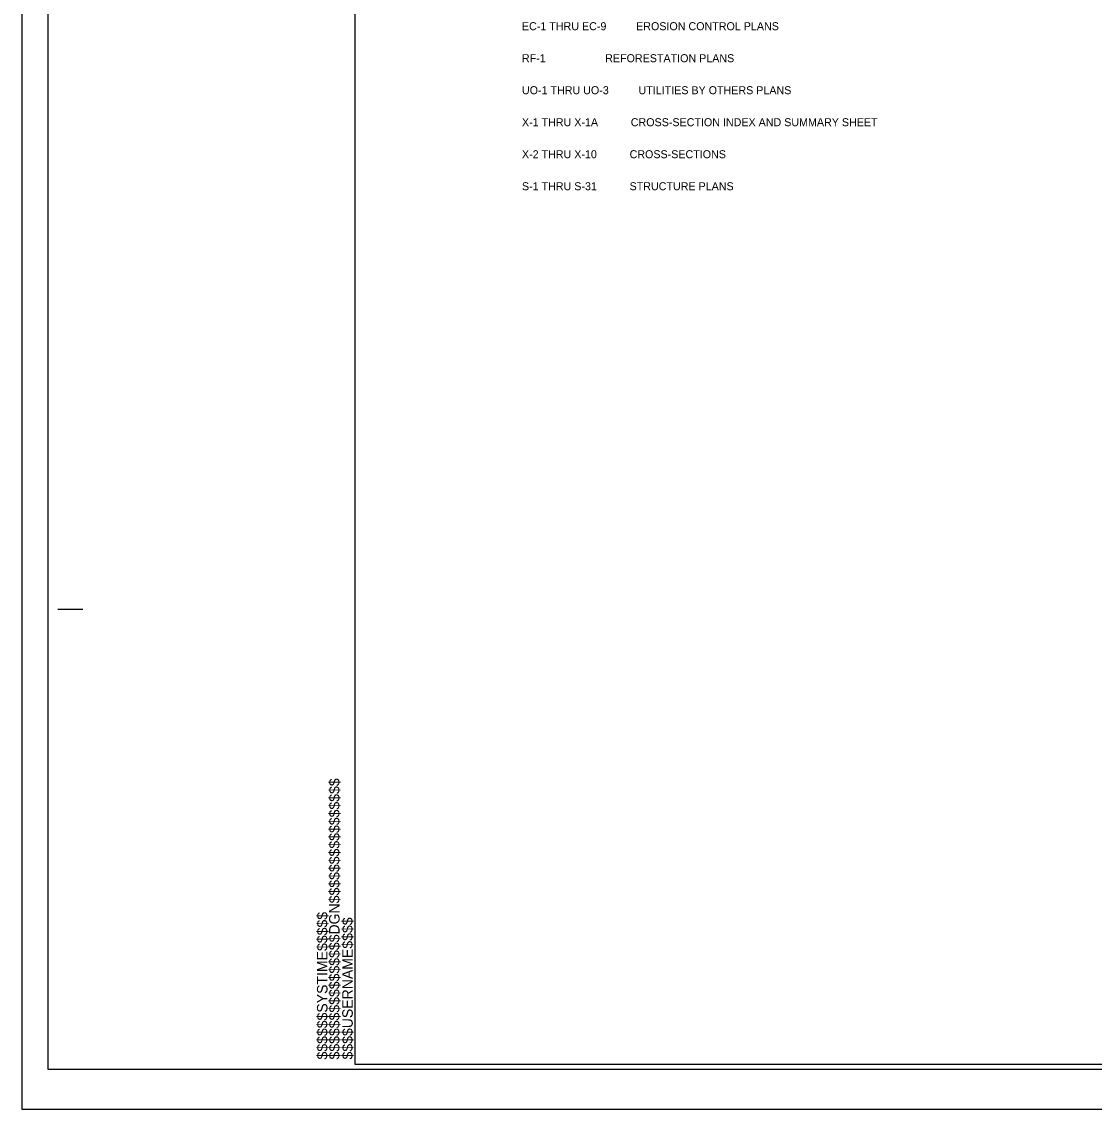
# Model space of a CAD drawing. Extents: x 1983800 to 2121016, y 627229 to 697309.
# Drawn here: x 1983800 to 2018104, y 627229 to 662023 of the extents above; entities that cross this region are included whole.
import ezdxf

# ---------------------------------------------------------------- set-up
doc = ezdxf.new("R2010")
doc.units = 0
for name, color, linetype in [('Sheet Cutting Line CELL', 7, 'Continuous'), ('Sheet Data Text CELL', 7, 'Continuous'), ('Sheet Plan CELL', 7, 'Continuous'), ('Sheet Plot Border Inside CELL', 7, 'Continuous'), ('Sheet Plot Border Outside CELL', 7, 'Continuous')]:
    doc.layers.add(name, color=color, linetype=linetype)

msp = doc.modelspace()

# ---------------------------------------------------------------- linework, layer by layer
at = {"layer": 'Sheet Cutting Line CELL'}
for p, q in [((1983800, 697309), (1983800, 627229)), ((1983800, 627229), (2091544, 627229))]:
    msp.add_line(p, q, dxfattribs=at)
at = {"layer": 'Sheet Plan CELL'}
for p, q in [((1984952, 643229), (1985752, 643229)), ((1994456, 628669), (1994456, 628669))]:
    msp.add_line(p, q, dxfattribs=at)
msp.add_lwpolyline([(2090456, 695869), (1994456, 695869), (1994456, 628669), (2090456, 628669)], close=True, dxfattribs=at)
at = {"layer": 'Sheet Plot Border Inside CELL'}
msp.add_lwpolyline([(1984632, 628509), (2091256, 628509), (2091256, 696029), (1984632, 696029)], close=True, dxfattribs=at)
at = {"layer": 'Sheet Plot Border Outside CELL'}
msp.add_lwpolyline([(1983800, 627229), (2091544, 627229), (2091544, 697309), (1983800, 697309)], close=True, dxfattribs=at)

# ---------------------------------------------------------------- texts
at = {"layer": 'Sheet Data Text CELL'}
for s, p in [('EC-1 THRU EC-9          EROSION CONTROL PLANS', (1999799, 661752)), ('RF-1                    REFORESTATION PLANS', (1999799, 660728)), ('UO-1 THRU UO-3          UTILITIES BY OTHERS PLANS', (1999799, 659704)), ('X-1 THRU X-1A           CROSS-SECTION INDEX AND SUMMARY SHEET', (1999799, 658680)), ('X-2 THRU X-10           CROSS-SECTIONS', (1999799, 657656)), ('S-1 THRU S-31           STRUCTURE PLANS', (1999799, 656632))]:
    msp.add_text(s, height=256, dxfattribs=at).set_placement(p)
at = {"layer": 'Sheet Plan CELL'}
for s, p in [('$$$$$$$$$$$$$$$$DGN$$$$$$$$$$$$$$$$', (1993966, 628820)), ('$$$$$$SYSTIME$$$$$', (1993579, 628820)), ('$$$$USERNAME$$$$', (1994387, 628821))]:
    msp.add_text(s, height=336, rotation=90, dxfattribs=at).set_placement(p)

doc.saveas('drawing.dxf')
